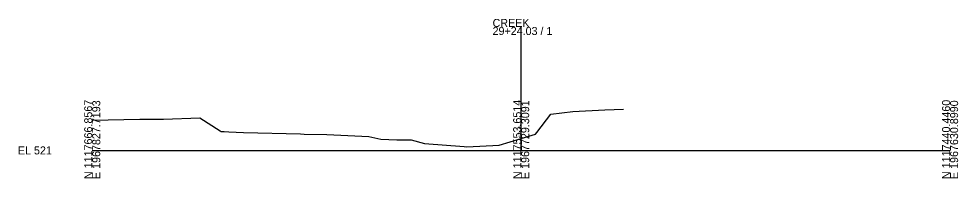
# Model space of a CAD drawing. Extents: x 9974 to 10303, y 9990 to 19550.
# Drawn here: x 9974.3 to 10302.8, y 18490.3 to 18545.9 of the extents above; entities that cross this region are included whole.
import ezdxf

# ---------------------------------------------------------------- set-up
doc = ezdxf.new("R2010")
doc.units = 0
for name, color, linetype in [('Level 10', 7, 'Continuous'), ('Level 60', 7, 'Continuous'), ('Level 63', 7, 'Continuous')]:
    doc.layers.add(name, color=color, linetype=linetype)

msp = doc.modelspace()

# ---------------------------------------------------------------- linework, layer by layer
at = {"layer": 'Level 60'}
for p, q in [((10160.33, 18512.61), (10168.07, 18513.55)), ((10168.07, 18513.55), (10179.23, 18514.18)), ((10179.23, 18514.18), (10185.84, 18514.37)), ((10000, 18510.53), (10016.61, 18510.89)), ((10016.61, 18510.89), (10024.96, 18510.87)), ((10024.96, 18510.87), (10037.58, 18511.34)), ((10037.58, 18511.34), (10044.72, 18506.87)), ((10155.44, 18506.21), (10160.33, 18512.61)), ((10044.72, 18506.87), (10045.08, 18506.62)), ((10045.08, 18506.62), (10046.11, 18506.59)), ((10046.11, 18506.59), (10047.73, 18506.54)), ((10047.73, 18506.54), (10052.86, 18506.25)), ((10052.86, 18506.25), (10072.86, 18505.84)), ((10072.86, 18505.84), (10074.1, 18505.71)), ((10074.1, 18505.71), (10082.07, 18505.52)), ((10082.07, 18505.52), (10096.74, 18504.82)), ((10096.74, 18504.82), (10100.89, 18503.97)), ((10100.89, 18503.97), (10106.55, 18503.72)), ((10106.55, 18503.72), (10111.5, 18503.64)), ((10111.5, 18503.64), (10116.22, 18502.39)), ((10142.32, 18501.89), (10150, 18504.16)), ((10150, 18504.16), (10155.02, 18505.66)), ((10155.02, 18505.66), (10155.44, 18506.21)), ((10116.22, 18502.39), (10130.09, 18501.33)), ((10130.09, 18501.33), (10130.95, 18501.26)), ((10130.95, 18501.26), (10142.32, 18501.89))]:
    msp.add_line(p, q, dxfattribs=at)
at = {"layer": 'Level 63'}
for p, q in [((10150, 18500), (10150, 18543.1)), ((10000, 18500), (10150, 18500)), ((10150, 18500), (10300, 18500))]:
    msp.add_line(p, q, dxfattribs=at)

# ---------------------------------------------------------------- texts
at = {"layer": 'Level 10'}
msp.add_text('525.163', height=0.8, rotation=90, dxfattribs=at).set_placement((10149.9, 18504.66))
at = {"layer": 'Level 63'}
for s, p in [('CREEK', (10140, 18543.1)), ('29+24.03 / 1', (10140, 18540.3)), ('EL 521', (9974, 18498.6))]:
    msp.add_text(s, height=2.8, dxfattribs=at).set_placement(p)
for s, p in [('N 1117666.8567', (10000, 18490)), ('E 1967827.7193', (10002.8, 18490)), ('N 1117553.6514', (10150, 18490)), ('E 1967729.3091', (10152.8, 18490)), ('N 1117440.4460', (10300, 18490)), ('E 1967630.8990', (10302.8, 18490))]:
    msp.add_text(s, height=2.8, rotation=90, dxfattribs=at).set_placement(p)

doc.saveas('drawing.dxf')
